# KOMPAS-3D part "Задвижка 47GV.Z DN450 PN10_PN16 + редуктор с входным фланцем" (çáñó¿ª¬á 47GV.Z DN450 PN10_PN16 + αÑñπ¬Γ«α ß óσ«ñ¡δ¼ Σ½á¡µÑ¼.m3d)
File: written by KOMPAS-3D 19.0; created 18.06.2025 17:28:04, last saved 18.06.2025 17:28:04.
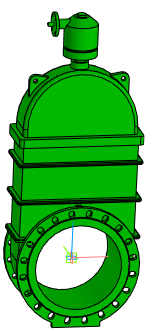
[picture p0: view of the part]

Document properties: Полное имя файла: Задвижка 47GV.Z DN450 PN10_PN16 + редуктор с входным валом.a3d

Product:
- Part/product: Задвижка 47GV.Z DN450 PN10_PN16 + редуктор с входным фланцем
    Масса: 970.943
  - Body: Тело 1
      Масса: 971.157

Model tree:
1. Операция без истории:1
